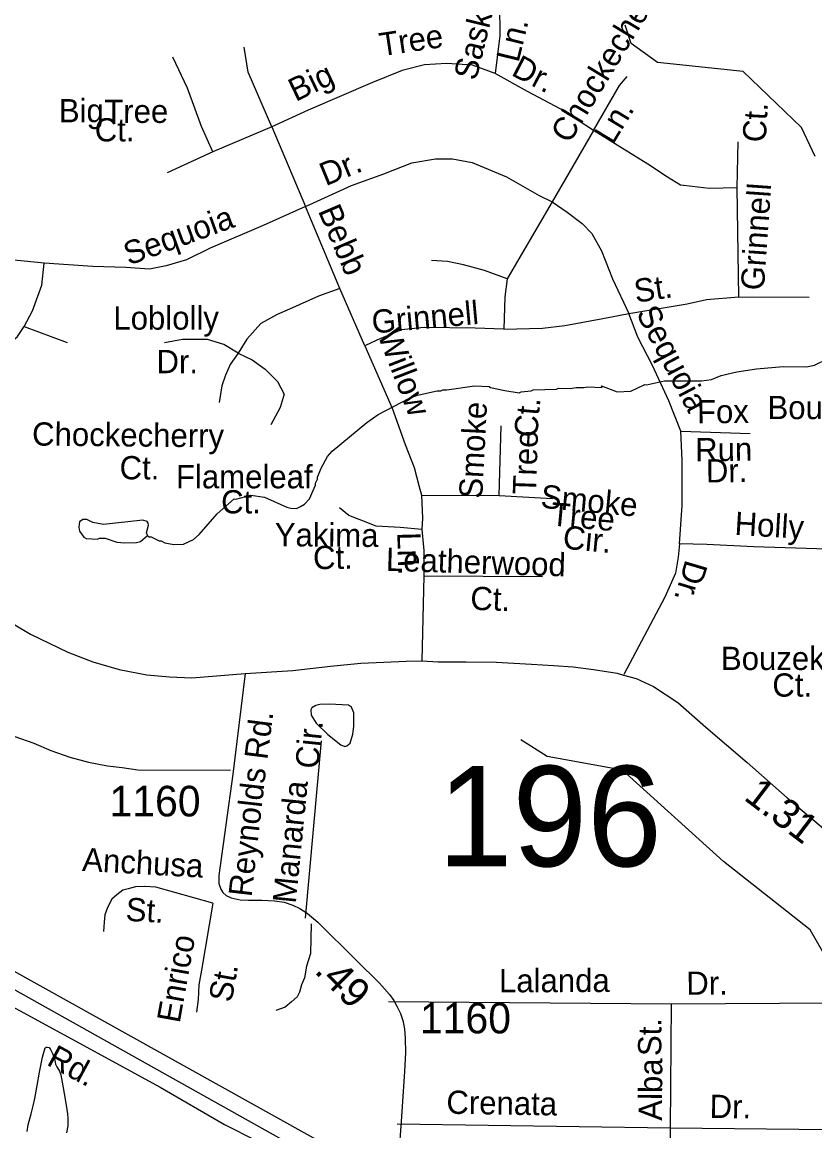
# Model space of a CAD drawing. Extents: x 1547597 to 1699558, y 810033 to 920809.
# Drawn here: x 1583442 to 1586678, y 851817 to 856344 of the extents above; entities that cross this region are included whole.
import ezdxf

# ---------------------------------------------------------------- set-up
doc = ezdxf.new("R2010")
doc.units = 0
for name, color, linetype in [('Exist Hydrographic Creek Single Shore', 7, 'Continuous'), ('Exist Hydrographic Misc Water Feature', 7, 'Continuous'), ('Exist Road Non-System Type 51', 7, 'Continuous'), ('Exist Road Non-System Type 51 Label', 7, 'Continuous'), ('Exist Road Primary US Divided Attributed', 7, 'Continuous'), ('Exist Road Secondary Mileage Hundredths English Label', 7, 'Continuous'), ('Exist Road Secondary Structure Standard Bridge Number Label', 7, 'Continuous'), ('Exist Road Secondary Type 51 Attributed', 7, 'Continuous'), ('Exist Road Secondary Type 51 Label', 7, 'Continuous'), ('Exist Road Secondary Type 51 Number Label', 7, 'Continuous')]:
    doc.layers.add(name, color=color, linetype=linetype)

msp = doc.modelspace()

# ---------------------------------------------------------------- linework, layer by layer
at = {"layer": 'Exist Hydrographic Creek Single Shore'}
for points in [[(1586679.3, 855795.9), (1586623.5, 855913.9), (1586385.5, 856142), (1586035.5, 856178.6), (1585928.6, 856256.3), (1585904.6, 856332.2)], [(1587235.3, 851702.6), (1587081.6, 851847.2), (1586861.6, 852166.8), (1586757.5, 852467.6), (1586659.6, 852637), (1586305.6, 852916.6), (1585893.5, 853289.4), (1585585.5, 853344.8), (1585478.5, 853412.7)]]:
    msp.add_lwpolyline(points, dxfattribs=at)
at = {"layer": 'Exist Hydrographic Misc Water Feature'}
for points in [[(1583953.2, 854248.4), (1583961.1, 854242.3), (1583969.1, 854242.2), (1584000.9, 854225.8), (1584008.9, 854225.7), (1584024.8, 854217.5), (1584060.8, 854211), (1584100.8, 854212.5), (1584140.9, 854232), (1584165.1, 854251.7), (1584238.1, 854336.7), (1584306.9, 854397.8), (1584313.8, 854396.3), (1584375, 854413), (1584431, 854404.3), (1584522.4, 854363.1), (1584538.4, 854358.9), (1584562.4, 854358.6), (1584578.4, 854366.5), (1584594.6, 854376.3), (1584614.8, 854398), (1584639.5, 854453.6), (1584639.6, 854461.6), (1584647.7, 854477.5), (1584647.8, 854485.5), (1584662.3, 854523.3), (1584688.8, 854571), (1584707.1, 854592.7), (1584849.4, 854709.4), (1584894.8, 854742.3), (1585023.6, 854808.7), (1585055.8, 854820.3), (1585136, 854839.2), (1585152, 854839), (1585160.1, 854842.9), (1585176, 854842.7), (1585289.4, 854858.5), (1585348.1, 854856.5), (1585354.4, 854851.8), (1585412, 854839.7), (1585471.8, 854831), (1585479.8, 854834.9), (1585519.9, 854838.4), (1585527.9, 854842.3), (1585624, 854845.1), (1585632, 854849), (1585680, 854848.4), (1585704.1, 854852.1), (1585735.9, 854851.7), (1585752, 854855.5), (1585810, 854852.8), (1585808, 854858.8), (1585871.8, 854834), (1585927.8, 854837.3), (1585984.1, 854864.5), (1585991, 854862.8), (1586064.2, 854879.5), (1586216.3, 854879.6), (1586256.3, 854885.1), (1586296.5, 854900.6), (1586360.6, 854915.8), (1586439.9, 854928), (1586548.9, 854937.4), (1586644.8, 854936.2), (1586676.9, 854943.8), (1586733.2, 854971.1)], [(1583953.2, 854248.4), (1583949.3, 854258.4), (1583957.7, 854290.3), (1583955.8, 854298.3), (1583951.9, 854304.3), (1583933.9, 854310.6), (1583773.8, 854292.6), (1583729.9, 854301.2), (1583706, 854313.5), (1583690, 854313.7), (1583675.9, 854303.8), (1583673.6, 854281.9), (1583675.5, 854265.8), (1583693.2, 854241.6), (1583703.1, 854235.5), (1583749.1, 854232.9), (1583757.1, 854236.8), (1583781.1, 854236.5), (1583828.9, 854220), (1583860.8, 854217.6), (1583908.8, 854218.9), (1583924.9, 854222.7), (1583953.2, 854248.4)], [(1584796.4, 853519.1), (1584796.4, 853524.1), (1584786.7, 853546.2), (1584774.8, 853554.3), (1584696.8, 853559.3), (1584656.9, 853557.8), (1584640.9, 853554), (1584624.7, 853544.2), (1584620.6, 853536.3), (1584622.3, 853514.3), (1584642, 853482), (1584689.4, 853435.5), (1584742.9, 853392.8), (1584758.8, 853386.6), (1584766.9, 853388.5), (1584780.9, 853400.3), (1584791.4, 853436.2), (1584795.8, 853468.1), (1584796.4, 853519.1)], [(1583462.7, 851813.8), (1583466.7, 851841.9), (1583478.9, 851886), (1583487.2, 851919.3), (1583493.1, 851949.2), (1583502.5, 852001.7), (1583512.3, 852056.6), (1583525.3, 852117.5), (1583535.6, 852155), (1583539.3, 852158.6), (1583544.1, 852158.5), (1583551.8, 852156.5), (1583557.1, 852149.2), (1583567, 852129.3), (1583574.9, 852105.8), (1583577.6, 852089.6), (1583582.8, 852077.5), (1583594.4, 852059.9), (1583599.7, 852046), (1583605.7, 852016)], [(1583605.7, 852016), (1583613.3, 851969.2), (1583622, 851921.1), (1583627.5, 851886.3), (1583628.9, 851866.5), (1583627.8, 851837.8), (1583623.1, 851809.1)]]:
    msp.add_lwpolyline(points, dxfattribs=at)
at = {"layer": 'Exist Road Non-System Type 51'}
for p, q in [((1584598.7, 852684.6), (1584664.6, 853409.3)), ((1584937.4, 852344.8), (1586091.3, 852335.3)), ((1586091.3, 852335.3), (1586755.8, 852339.7)), ((1586091.3, 852335.3), (1586088.1, 851829.1)), ((1584972.4, 851845.1), (1586088.1, 851829.1)), ((1586088.1, 851829.1), (1586085.7, 851661.1)), ((1586088.1, 851829.1), (1586744.3, 851821.6))]:
    msp.add_line(p, q, dxfattribs=at)
for points in [[(1585390.7, 856414.6), (1585392.5, 856289.7), (1585372.9, 856134.6)], [(1584461.1, 855917.1), (1584364.7, 856140.4), (1584349, 856241.8)], [(1584220.7, 855813.9), (1584173.5, 855917.5), (1584117.2, 856075.1), (1584056.5, 856201.2)], [(1585372.9, 856134.6), (1585280.2, 856168.5), (1585175.1, 856175.6), (1585084.2, 856170.2), (1584993.3, 856147.1), (1584872.2, 856097.1), (1584610.2, 855984.7), (1584461.1, 855917.1)], [(1585775.1, 855901.5), (1585642, 855988.3), (1585504.8, 856061.4), (1585372.9, 856134.6)], [(1585775.1, 855901.5), (1585880.3, 856085.2), (1585912.3, 856122.7)], [(1584461.1, 855917.1), (1584220.7, 855813.9)], [(1584461.1, 855917.1), (1584598.3, 855591.4)], [(1585775.1, 855901.5), (1585606, 855609.7)], [(1586360.7, 855666.9), (1586247.4, 855664.3), (1586177.9, 855673.2), (1586129.7, 855678.6), (1586076.3, 855710.7), (1585996.1, 855764.2), (1585775.1, 855901.5)], [(1586360.7, 855666.9), (1586365, 855855.1)], [(1584220.7, 855813.9), (1584034, 855728.4)], [(1584598.3, 855591.4), (1584787.2, 855677), (1584919.1, 855725.2), (1585033.1, 855769.8), (1585129.3, 855785.8), (1585198.8, 855785.8), (1585279, 855771.6), (1585419.8, 855712.7), (1585553.5, 855636), (1585606, 855609.7)], [(1586367.8, 855222.8), (1586360.7, 855666.9)], [(1585606, 855609.7), (1585422.7, 855295.8)], [(1585606, 855609.7), (1585666.6, 855568.6), (1585729, 855522.3), (1585768.2, 855481.2), (1585807.4, 855409.9), (1585851.9, 855295.7), (1585918.8, 855154.2)], [(1584598.3, 855591.4), (1584425.5, 855513), (1584209.5, 855420.6), (1584112.8, 855373.4), (1584029.5, 855348.6), (1583962, 855335.1), (1583865.3, 855341.8), (1583730.3, 855346.3), (1583532.3, 855359.9)], [(1584739.2, 855257), (1584598.3, 855591.4)], [(1583532.3, 855359.9), (1583324.4, 855380.7), (1583142.2, 855380.7), (1583047.7, 855378.5)], [(1585422.7, 855295.8), (1585330, 855329.7), (1585244.5, 855352.9), (1585178.5, 855367.2), (1585112.6, 855370.7)], [(1583450.4, 855101.3), (1583484.2, 855164.6), (1583522.4, 855270.4), (1583532.3, 855359.9)], [(1585422.7, 855295.8), (1585412, 855222.7), (1585408.4, 855090.7)], [(1584739.2, 855257), (1584652.1, 855224.9), (1584533.3, 855172.6), (1584483, 855150.1), (1584416.4, 855113.2), (1584358.8, 855049.2), (1584323.9, 854992.1)], [(1584840.8, 855021.6), (1584739.2, 855257)], [(1585918.8, 855154.2), (1586157.5, 855194.3), (1586235.9, 855212.1), (1586367.8, 855222.8)], [(1586367.8, 855222.8), (1586654.7, 855221)], [(1585408.4, 855090.7), (1585567, 855094.3), (1585657.9, 855105), (1585812.9, 855133.5), (1585918.8, 855154.2)], [(1586130.8, 854673.5), (1586082.7, 854797.5), (1586015, 854942), (1585956.2, 855057.9), (1585918.8, 855154.2)], [(1582737.2, 855072), (1582795.7, 855018.2), (1582897, 854984.4), (1583119.7, 854970.9), (1583279.4, 854975.4), (1583378.4, 855020.4), (1583423.4, 855061), (1583450.4, 855101.3)], [(1583450.4, 855101.3), (1583625.9, 855036)], [(1585408.4, 855090.7), (1585291.6, 855094.7), (1585083.1, 855096.5), (1584990.4, 855087.6), (1584890.6, 855044.8), (1584840.8, 855021.6)], [(1584323.9, 854992.1), (1584265.7, 855027.5), (1584198.2, 855047.8), (1584135.2, 855047.8), (1584097, 855047.8), (1584022.7, 855034.3)], [(1584840.8, 855021.6), (1584952.7, 854767.4), (1585006.1, 854619.4), (1585041.8, 854524.8), (1585061.4, 854451.7), (1585072.1, 854412.5)], [(1584323.9, 854992.1), (1584291.6, 854946.6), (1584272.7, 854902.4), (1584256.5, 854858.3), (1584246.6, 854790.7)], [(1584323.9, 854992.1), (1584380.7, 854965.5), (1584433.8, 854926.8), (1584484.1, 854877.2), (1584511.1, 854825), (1584495.8, 854770.9), (1584457.1, 854699.8)], [(1585389.3, 854410.7), (1585398.2, 854696.1)], [(1586125.8, 854213.3), (1586136.2, 854370.3), (1586136.2, 854555.8), (1586130.8, 854673.5)], [(1586130.8, 854673.5), (1586414.2, 854664.6)], [(1585072.1, 854412.5), (1585389.3, 854410.7)], [(1585072.1, 854412.5), (1585076.4, 854318.1), (1585073.6, 854272.2)], [(1585389.3, 854410.7), (1585606.7, 854398.2)], [(1585073.6, 854272.2), (1584984.7, 854280.8), (1584887.1, 854286.5), (1584835.5, 854306.6), (1584775.3, 854329.6), (1584738, 854361.2)], [(1585073.6, 854272.2), (1585082.2, 854186), (1585082.2, 854082.7)], [(1586125.8, 854213.3), (1586120.6, 854159.7), (1586109.2, 854094.4), (1586065.8, 853995.9), (1585898.2, 853680.5)], [(1586814.7, 854189.9), (1586429.1, 854202.1), (1586237.3, 854211), (1586125.8, 854213.3)], [(1585082.2, 854082.7), (1585073.6, 853735.4)], [(1585082.2, 854082.7), (1585566.9, 854079.8)], [(1583104.7, 853495.1), (1583166.6, 853490.2), (1583232.7, 853479.3), (1583320.3, 853457.9), (1583411.9, 853426.6), (1583489.6, 853399.4), (1583559, 853370.4), (1583636.7, 853343.2), (1583712.6, 853322), (1583790.3, 853307.1), (1583850.2, 853300.1), (1583914.2, 853291.1), (1584292.4, 853289.7)], [(1584220.2, 852746), (1583987.4, 852812), (1583943.2, 852814.5), (1583905.2, 852813.1), (1583875.2, 852805.5), (1583858.7, 852801.3), (1583853.1, 852799.9), (1583828.7, 852780.2), (1583808.5, 852762.6), (1583790, 852728.7), (1583779.6, 852698.9), (1583777.2, 852669), (1583774.6, 852631)], [(1584220.2, 852746), (1584174.4, 852473), (1584163.6, 852413.2), (1584160.8, 852353.2), (1584153.9, 852301.3)], [(1584621.6, 852661.8), (1584619.2, 852540.3), (1584602.3, 852488.6), (1584595, 852441), (1584582.5, 852413.3), (1584574.7, 852382.7), (1584565.1, 852363.5), (1584541.1, 852343), (1584516.4, 852322), (1584478.3, 852308.6)]]:
    msp.add_lwpolyline(points, dxfattribs=at)
at = {"layer": 'Exist Road Primary US Divided Attributed'}
for points in [[(1584974.1, 851611.8), (1584724.8, 851735.3), (1582795.5, 852809.6), (1582416.9, 853010.1), (1582179.2, 853141), (1582040, 853216.5), (1581899.7, 853287.3), (1581755.2, 853359.2), (1581610.1, 853431.2), (1581464.4, 853496.1), (1581249.7, 853586.9), (1581019.1, 853682.4), (1580837.5, 853756.7), (1580615.2, 853838.1), (1580421.7, 853906.5), (1580197, 853983.2), (1578615.9, 854532.9)], [(1578489.7, 854501), (1578601.1, 854463.3), (1580008.3, 853986.7), (1580472.4, 853825.1), (1580622.2, 853773.2), (1580843.4, 853691.9), (1581027.4, 853617.5), (1581220.2, 853535), (1581440.8, 853444.2), (1581580.6, 853375.7), (1581724.5, 853303.8), (1581891.4, 853228.3), (1582021.1, 853157.5), (1582160.3, 853082), (1582406.3, 852952.3), (1582786.1, 852742.3), (1584705.4, 851668.3), (1584967.6, 851548.7)]]:
    msp.add_lwpolyline(points, dxfattribs=at)
at = {"layer": 'Exist Road Secondary Type 51 Attributed'}
for points in [[(1581306.1, 856387.5), (1581459.7, 856183.6), (1581746.8, 855793.5), (1582252, 855129.1), (1582535.1, 854745.8), (1582782.2, 854419.6), (1582840.6, 854337), (1582940, 854210.3), (1582983.6, 854166.6), (1583057.6, 854097.6), (1583107.8, 854065.2), (1583190.9, 854013.9), (1583476.4, 853845.2), (1583627.9, 853770.9), (1583730.6, 853732), (1583837.6, 853700.7), (1583951.4, 853678.3), (1584043.1, 853670), (1584135.1, 853665.9), (1584352.8, 853684.2)], [(1584352.8, 853684.2), (1584546.4, 853696.2), (1584700.6, 853714.1), (1584825, 853726.2), (1584919.1, 853730.9), (1585010.4, 853735), (1585073.6, 853735.4), (1585141.1, 853731.6), (1585255.1, 853732.1), (1585377.2, 853730.2), (1585521.3, 853722.1), (1585611.2, 853716.8), (1585691.2, 853711.6), (1585775, 853700.5), (1585870.7, 853685), (1585896.8, 853678), (1585948.5, 853664), (1586020.1, 853630.9), (1586119.2, 853565.5), (1586233.7, 853465.7), (1586401.9, 853321.2), (1586565.8, 853176.8), (1586844.1, 852941.6)], [(1584352.8, 853684.2), (1584302.6, 853273.1), (1584244.8, 852859.1), (1584244.8, 852827.3), (1584253.1, 852803.7), (1584261.3, 852789.5), (1584274.3, 852777.7), (1584295, 852768.3), (1584331.5, 852760), (1584366.3, 852758.3), (1584420, 852758.3), (1584472.8, 852755.3), (1584511.1, 852750), (1584547.1, 852738.2), (1584576, 852724.1), (1584605.5, 852705.8), (1584649.1, 852668.6), (1584805.7, 852513.5), (1584901.2, 852419.1), (1584941.6, 852373.1), (1584959.3, 852348.4), (1584972.3, 852326), (1584987, 852295.3), (1584996.5, 852267.6), (1585003, 852233.4), (1585005.9, 852194.4), (1585007.7, 852136.7), (1585003.6, 852058.8), (1584988.8, 851855.3), (1584979.4, 851724.4)], [(1582354.7, 851683.1), (1582382.4, 852027), (1582416.6, 852392.6), (1582441.1, 852647.4), (1582450.5, 852677.5), (1582463.5, 852702.2), (1582477.6, 852721.7), (1582490.6, 852734.7), (1582518.9, 852754.1), (1582536, 852757.7), (1582578.5, 852758.9), (1582609.7, 852752.4), (1582632.1, 852742.3), (1582710.3, 852700.5), (1583205.1, 852430.4), (1584005.1, 851995.1), (1584268.4, 851843.1), (1584397, 851777.5)]]:
    msp.add_lwpolyline(points, dxfattribs=at)

# ---------------------------------------------------------------- texts
at = {"layer": 'Exist Road Non-System Type 51 Label'}
for s, rotation, p in [('Saskatoon', 76.1847, (1585295.5, 856102.3)), ('Chockecherry', 58.7138, (1585675.8, 855844)), ('Ln.', 76.3436, (1585468.4, 856176)), ('Tree', 8.471, (1584907.5, 856204.4)), ('Dr.', 332.6812, (1585434.6, 856129.2)), ('Big', 25.6351, (1584558.4, 856017.7)), ('Ln.', 58.7138, (1585852.9, 855839.2)), ('Ct.', 86.8938, (1586478, 855851.5)), ('Dr.', 22.314, (1584681.1, 855673.6)), ('Grinnell', 86.0104, (1586470.3, 855246.5)), ('Bebb', 293.1729, (1584648.6, 855573.7)), ('Sequoia', 19.9467, (1583877.1, 855349.7)), ('St.', 8.496, (1585947.8, 855198)), ('Grinnell', 5.2209, (1584873.4, 855072.2)), ('Sequoia', 297.7796, (1585947, 855155.6)), ('Willow', 291.1496, (1584891.5, 855067.9)), ('Smoke', 87.0593, (1585320, 854396.9)), ('Ct.', 85.1351, (1585544.7, 854645.6)), ('Fox', 0.7095, (1586197.9, 854705.2)), ('Chockecherry', 359.4375, (1583482.1, 854615.2)), ('Tree', 88.0923, (1585539.7, 854414)), ('Run', 0.7095, (1586190.3, 854550.5)), ('Ct.', 359.736, (1583839.5, 854477.3)), ('Dr.', 0.7095, (1586234.2, 854464.2)), ('Smoke', 354.6347, (1585556.5, 854361.5)), ('Tree', 354.6347, (1585597.3, 854289.5)), ('Holly', 356.6152, (1586349.1, 854250.5)), ('Yakima', 359.563, (1584473, 854204)), ('Cir.', 354.6347, (1585646.7, 854194.5)), ('Ln.', 271.435, (1584973.5, 854260.4)), ('Ct.', 0.6713, (1584630, 854110)), ('Leatherwood', 358.1822, (1584926, 854103.8)), ('Dr.', 253.4306, (1586151.2, 854152.8)), ('Ct.', 358.1822, (1585270.7, 853944.4)), ('Cir.', 84.3331, (1584650.8, 853292.3)), ('Manarda', 84.3331, (1584559, 852742.8)), ('Anchusa', 356.7627, (1583685.3, 852878.4)), ('St.', 356.7627, (1583862.8, 852674.6)), ('Enrico', 79.7652, (1584084.8, 852253.4)), ('St.', 79.7652, (1584296.7, 852338.4)), ('Lalanda', 0.1941, (1585389, 852382.1)), ('Dr.', 0.3793, (1586153.9, 852372)), ('St.', 89.6376, (1586051.4, 852121.9)), ('Alba', 89.6376, (1586054.3, 851857.9)), ('Crenata', 359.0682, (1585173.5, 851886.6)), ('Dr.', 359.3452, (1586248.4, 851869.5))]:
    msp.add_text(s, height=95, rotation=rotation, dxfattribs=at).set_placement(p)
for s, p in [('Big', (1583591.7, 855935.1)), ('Tree', (1583777.1, 855932.5)), ('Ct.', (1583738.1, 855856.9)), ('Loblolly', (1583814.3, 855088.5)), ('Dr.', (1583990.4, 854910.6)), ('Bouzeke', (1586485.2, 854723.1)), ('Flameleaf', (1584069.9, 854440.4)), ('Ct.', (1584254.3, 854337.9)), ('Bouzeke', (1586295.1, 853698.6)), ('Ct.', (1586505, 853589.7))]:
    msp.add_text(s, height=95, dxfattribs=at).set_placement(p)
at = {"layer": 'Exist Road Secondary Mileage Hundredths English Label'}
for s, rotation, p in [('1.31', 322.7313, (1586384, 853172)), ('.49', 315.2192, (1584631.3, 852465.1))]:
    msp.add_text(s, height=120, rotation=rotation, dxfattribs=at).set_placement(p)
at = {"layer": 'Exist Road Secondary Structure Standard Bridge Number Label'}
msp.add_text('196', height=410.1, dxfattribs=at).set_placement((1585138.9, 852896.9))
at = {"layer": 'Exist Road Secondary Type 51 Label'}
for s, rotation, p in [('Rd.', 82.7187, (1584442.9, 853329.4)), ('Reynolds', 83.4995, (1584378.3, 852769.3)), ('Rd.', 331.5658, (1583537.4, 852088.1))]:
    msp.add_text(s, height=95, rotation=rotation, dxfattribs=at).set_placement(p)
at = {"layer": 'Exist Road Secondary Type 51 Number Label'}
for p in [(1583798.5, 853100.7), (1585065.9, 852214.7)]:
    msp.add_text('1160', height=125, dxfattribs=at).set_placement(p)

doc.saveas('drawing.dxf')
